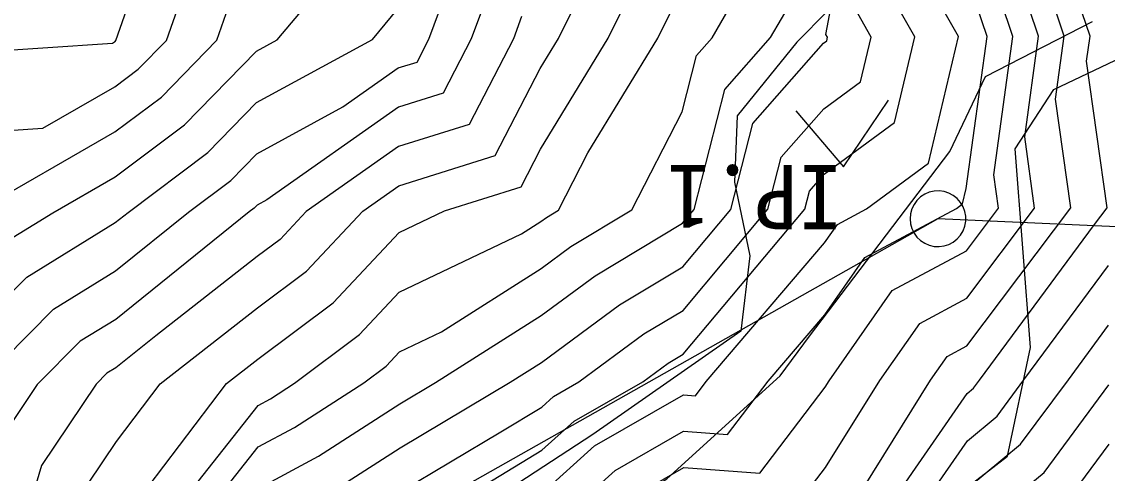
# Model space of a CAD drawing. Extents: x 42655 to 43811, y -141820 to -141156.
# Drawn here: x 43241.93 to 43280.88, y -141342.18 to -141325.97 of the extents above; entities that cross this region are included whole.
import ezdxf

# ---------------------------------------------------------------- set-up
doc = ezdxf.new("R2010")
doc.units = 0
for name, color, linetype in [('D-BMK-HTXT_1', 7, 'Continuous'), ('ZE_HICN', 7, 'Continuous'), ('ZE_LWCN', 7, 'Continuous'), ('地形', 7, 'Continuous')]:
    doc.layers.add(name, color=color, linetype=linetype)

msp = doc.modelspace()

# ---------------------------------------------------------------- linework, layer by layer
at = {"layer": 'D-BMK-HTXT_1'}
for p, q in [((43274.802, -141333.044), (43130.975, -141414.265)), ((43439.808, -141340.537), (43274.802, -141333.044))]:
    msp.add_line(p, q, dxfattribs=at)
msp.add_lwpolyline([(43273.802, -141333.044), (43273.818, -141333.222), (43273.866, -141333.395), (43273.944, -141333.557), (43274.049, -141333.702), (43274.179, -141333.826), (43274.328, -141333.924), (43274.493, -141333.995), (43274.668, -141334.035), (43274.847, -141334.043), (43275.025, -141334.019), (43275.195, -141333.963), (43275.353, -141333.878), (43275.493, -141333.766), (43275.611, -141333.631), (43275.703, -141333.478), (43275.766, -141333.31), (43275.798, -141333.133), (43275.798, -141332.954), (43275.766, -141332.778), (43275.703, -141332.61), (43275.611, -141332.456), (43275.493, -141332.321), (43275.353, -141332.209), (43275.195, -141332.124), (43275.025, -141332.069), (43274.847, -141332.045), (43274.668, -141332.053), (43274.493, -141332.093), (43274.328, -141332.163), (43274.179, -141332.262), (43274.049, -141332.386), (43273.944, -141332.531), (43273.866, -141332.692), (43273.818, -141332.865), (43273.802, -141333.044)], dxfattribs=at)
at = {"layer": 'ZE_HICN'}
for points in [[(43241.9, -141357.482), (43242.545, -141354.033), (43242.859, -141351.315), (43244.774, -141345.842), (43244.841, -141345.143), (43244.975, -141344.693), (43245.343, -141344.144), (43249.284, -141338.959), (43250.403, -141338.087), (43253.103, -141336.06), (43255.47, -141333.538), (43257.102, -141332.76), (43259.846, -141331.894), (43260.544, -141330.544), (43262.971, -141326.569), (43265.588, -141321.254)], [(43249.689, -141374.859), (43250.57, -141373.588), (43252.624, -141369.757), (43253.076, -141366.667), (43253.74, -141363.589), (43254.854, -141358.308), (43255.054, -141357.42), (43255.176, -141356.93), (43255.574, -141355.76), (43257.228, -141351.247), (43258.712, -141348.917), (43260.625, -141347.681), (43263.355, -141345.055), (43264.697, -141343.841), (43265.692, -141343.273), (43269.564, -141343.552), (43270.774, -141341.968), (43272.722, -141338.849), (43274.151, -141336.8), (43275.833, -141335.898), (43278.271, -141332.66), (43277.915, -141330.107), (43278.412, -141326.496), (43276.737, -141321.518)], [(43240.222, -141337.046), (43242.119, -141335.138), (43245.292, -141333.18), (43245.747, -141332.813), (43248.609, -141330.669), (43250.36, -141328.873), (43254.515, -141326.609), (43255.432, -141325.517)], [(43255.514, -141342.839), (43259.123, -141340.691), (43260.587, -141339.802), (43261.011, -141339.419), (43261.919, -141338.9), (43264.25, -141337.177), (43265.659, -141336.332), (43268.703, -141332.705), (43269.18, -141330.836), (43270.713, -141329.097), (43272.029, -141328.126), (43272.408, -141326.525), (43271.711, -141325.298)], [(43255.992, -141375.904), (43258.278, -141372.907), (43260.154, -141369.721), (43260.702, -141364.205), (43260.778, -141363.65), (43260.782, -141363.556), (43260.851, -141363.37), (43263.775, -141357.379), (43264.16, -141355.452), (43265.75, -141355.603), (43268.727, -141354.803), (43269.864, -141351.187), (43270.813, -141350.209), (43274.319, -141349.256), (43275.461, -141344.998), (43275.874, -141344.402), (43278.608, -141342.146), (43280.936, -141339.002)]]:
    msp.add_lwpolyline(points, dxfattribs=at)
at = {"layer": 'ZE_LWCN'}
for points in [[(43240.175, -141327.08), (43245.186, -141326.744), (43245.261, -141326.701), (43245.286, -141326.683), (43245.315, -141326.652), (43246.81, -141322.384), (43248.943, -141320.473), (43247.199, -141318.085), (43247.631, -141314.316), (43246.886, -141312.269), (43245.187, -141310.867), (43243.771, -141308.172), (43243.443, -141304.083), (43240.962, -141302.022)], [(43253.438, -141342.59), (43255.506, -141341.262), (43259.458, -141338.911), (43260.58, -141338.199), (43263.379, -141336.132), (43265.652, -141334.768), (43267.378, -141332.711), (43268.167, -141329.62), (43270.702, -141326.745), (43270.811, -141326.664), (43270.842, -141326.532), (43270.785, -141326.431), (43271.933, -141320.364)], [(43263.96, -141342.957), (43265.686, -141341.97), (43268.409, -141342.166), (43270.76, -141339.088), (43270.905, -141338.857), (43273.165, -141335.617), (43275.825, -141334.191), (43276.973, -141332.666), (43276.806, -141331.464), (43277.488, -141326.501), (43275.765, -141321.378)], [(43241.16, -141333.989), (43243.045, -141332.826), (43245.284, -141331.541), (43247.778, -141329.672), (43250.351, -141327.033), (43251.1, -141326.625), (43255.413, -141321.489)], [(43240.379, -141339.001), (43243.077, -141336.288), (43245.3, -141334.916), (43247.921, -141332.803), (43249.439, -141331.665), (43250.368, -141330.713), (43253.452, -141329.033), (43255.442, -141327.634), (43256.118, -141327.421), (43256.543, -141326.6), (43257.773, -141323.279)], [(43260.602, -141342.891), (43262.486, -141341.188), (43265.673, -141339.364), (43266.099, -141339.395), (43266.493, -141338.878), (43270.736, -141333.907), (43271.194, -141333.251), (43272.244, -141332.688), (43274.466, -141331.049), (43275.539, -141326.51), (43273.564, -141323.032)], [(43240.363, -141367.073), (43242.073, -141365.722), (43242.784, -141363.64), (43243.351, -141359.979), (43244.112, -141357.471), (43244.35, -141356.199), (43244.915, -141351.305), (43245.371, -141350.001), (43247.014, -141347.139), (43247.341, -141345.131), (43250.418, -141341.231), (43251.721, -141340.53), (43254.205, -141338.936), (43255.002, -141338.338), (43255.49, -141337.817), (43256.99, -141337.102), (43260.564, -141334.831), (43261.635, -141334.04), (43263.823, -141332.728), (43265.626, -141329.205), (43266.14, -141327.189), (43266.702, -141326.552), (43268.346, -141323.708)], [(43250.656, -141375.837), (43253.918, -141369.751), (43254.177, -141367.987), (43255.126, -141363.582), (43255.601, -141361.333), (43256.265, -141358.237), (43256.781, -141357.412), (43257.326, -141355.285), (43258.808, -141351.24), (43259.605, -141349.988), (43260.632, -141349.325), (43265.079, -141345.047), (43265.435, -141344.726), (43265.698, -141344.575), (43270.719, -141344.937), (43270.787, -141344.848), (43274.539, -141338.84), (43275.137, -141337.982), (43275.841, -141337.605), (43279.569, -141332.654), (43279.024, -141328.751), (43279.335, -141326.492), (43278.288, -141323.378)], [(43240.189, -141329.959), (43242.694, -141329.792), (43245.269, -141328.314), (43246.117, -141327.679), (43247.126, -141326.644), (43248.083, -141323.911)], [(43256.606, -141343.769), (43260.595, -141341.346), (43261.748, -141340.303), (43264.221, -141338.889), (43265.122, -141338.223), (43265.667, -141337.896), (43270.028, -141332.699), (43270.193, -141332.051), (43270.724, -141331.449), (43273.248, -141329.587), (43273.973, -141326.517), (43272.638, -141324.165)], [(43260.609, -141344.435), (43263.223, -141342.072), (43265.68, -141340.667), (43267.254, -141340.78), (43268.715, -141338.868), (43270.748, -141336.486), (43272.18, -141334.434), (43275.464, -141332.673), (43275.684, -141332.511), (43275.815, -141331.958), (43276.565, -141326.505), (43275.778, -141324.167)], [(43258.819, -141324.535), (43258.057, -141326.592), (43257.05, -141328.539), (43255.449, -141329.044), (43250.732, -141332.359), (43250.377, -141332.552), (43250.27, -141332.662), (43250.095, -141332.793), (43245.308, -141336.652), (43244.035, -141337.437), (43242.49, -141338.991), (43241.478, -141340.498)], [(43241.594, -141362.127), (43243.006, -141357.477), (43243.448, -141355.116), (43243.887, -141351.31), (43245.357, -141347.108), (43246.022, -141345.949), (43246.155, -141345.136), (43250.411, -141339.743), (43250.862, -141339.5), (43251.723, -141338.948), (43254.052, -141337.199), (43255.48, -141335.677), (43259.864, -141333.587), (43260.556, -141333.147), (43260.763, -141332.994), (43261.187, -141332.74), (43262.241, -141330.681), (43264.756, -141326.561), (43265.605, -141324.837)], [(43241.831, -141351.32), (43242.98, -141348.036), (43243.256, -141345.15), (43243.81, -141343.294), (43245.329, -141341.032), (43246.896, -141338.97), (43250.394, -141336.242), (43252.153, -141334.921), (43254.169, -141332.773), (43255.462, -141331.865), (43258.914, -141330.775), (43260.53, -141327.651), (43261.186, -141326.578), (43262.182, -141324.555)], [(43240.373, -141369.074), (43243.082, -141366.933), (43244.209, -141363.634), (43245.108, -141357.831), (43245.218, -141357.466), (43245.253, -141357.281), (43245.399, -141356.01), (43246.301, -141351.298), (43248.006, -141348.329), (43248.527, -141345.125), (43250.425, -141342.72), (43252.579, -141341.56), (43255.499, -141339.686), (43256.781, -141338.924), (43260.572, -141336.515), (43262.507, -141335.086), (43265.644, -141333.204), (43266.053, -141332.717), (43267.153, -141328.404), (43268.796, -141326.542), (43269.579, -141325.187)], [(43271.903, -141345.015), (43275.85, -141339.309), (43276.083, -141339.117), (43276.294, -141338.832), (43280.417, -141333.246), (43280.867, -141332.648), (43280.134, -141327.394), (43280.259, -141326.488), (43279.838, -141325.239)], [(43240.202, -141332.839), (43245.277, -141329.927), (43246.947, -141328.676), (43248.937, -141326.635), (43249.356, -141325.438)], [(43259.866, -141325.79), (43259.571, -141326.585), (43257.982, -141329.657), (43255.455, -141330.455), (43252.142, -141332.783), (43251.204, -141333.782), (43250.386, -141334.396), (43246.741, -141337.239), (43245.316, -141338.388), (43244.993, -141338.587), (43244.601, -141338.981), (43242.644, -141341.896), (43241.671, -141345.158)], [(43253.251, -141375.916), (43255.648, -141371.394), (43256.302, -141370.537), (43256.773, -141369.737), (43256.929, -141368.166), (43257.937, -141363.569), (43258.505, -141360.923), (43260.671, -141357.456), (43260.701, -141357.393), (43261.682, -141352.479), (43265.737, -141352.864), (43266.859, -141352.562), (43267.288, -141351.2), (43270.8, -141347.575), (43272.527, -141347.106), (43273.089, -141345.01), (43275.858, -141341.007), (43276.925, -141340.126), (43277.889, -141338.824), (43280.916, -141334.723)], [(43254.572, -141375.91), (43255.66, -141373.859), (43257.29, -141371.722), (43258.463, -141369.729), (43258.853, -141365.814), (43259.346, -141363.562), (43259.624, -141362.267), (43260.685, -141360.568), (43262.238, -141357.386), (43262.921, -141353.966), (43265.744, -141354.233), (43267.793, -141353.683), (43268.576, -141351.194), (43270.807, -141348.892), (43273.423, -141348.181), (43274.275, -141345.004), (43275.866, -141342.705), (43277.766, -141341.136), (43279.484, -141338.817), (43280.926, -141336.863)], [(43257.891, -141375.895), (43259.266, -141374.092), (43260.737, -141371.593), (43262.241, -141369.711), (43262.746, -141366.011), (43262.85, -141363.546), (43264.655, -141358.718), (43265.313, -141357.372), (43265.399, -141356.938), (43265.756, -141356.972), (43269.66, -141355.923), (43270.822, -141352.23), (43272.102, -141351.177), (43275.215, -141350.331), (43275.89, -141347.817), (43277.226, -141344.99), (43279.449, -141343.155), (43280.946, -141341.134)]]:
    msp.add_lwpolyline(points, dxfattribs=at)
at = {"layer": '地形'}
for points in [[(43273.079, -141323.322), (43269.743, -141326.702), (43267.594, -141329.35), (43267.503, -141331.725), (43268.052, -141334.374), (43267.728, -141337.079), (43262.426, -141340.779), (43256.21, -141344.843), (43254.244, -141347.766), (43251.365, -141351.191), (43254.566, -141352.527)], [(43259.49, -141353.323), (43254.566, -141352.527), (43255.16, -141350.289), (43257.446, -141347.275), (43265.079, -141342.38), (43269.147, -141338.68), (43270.2, -141337.253), (43275.228, -141330.629), (43276.508, -141327.935), (43280.347, -141325.971)], [(43294.351, -141331.831), (43287.212, -141332.387), (43284.616, -141334.517), (43283.225, -141336.926), (43283.04, -141340.261), (43281.649, -141344.615), (43277.477, -141350.173), (43268.484, -141357.862), (43265.795, -141360.456), (43262.364, -141362.216), (43259.675, -141361.29), (43259.954, -141358.047), (43259.49, -141353.323), (43267.278, -141348.135), (43273.583, -141344.43), (43277.292, -141341.558), (43278.126, -141337.667), (43277.57, -141330.534), (43278.96, -141328.403), (43282.854, -141326.551), (43290.086, -141326.643), (43295.186, -141327.014), (43294.351, -141331.831)], [(43269.704, -141329.176), (43271.412, -141331.179), (43273.032, -141328.79)]]:
    msp.add_lwpolyline(points, dxfattribs=at)

# ---------------------------------------------------------------- texts
at = {"layer": 'D-BMK-HTXT_1'}
msp.add_text('IP.1', height=2.3065, rotation=179.9992, dxfattribs=at).set_placement((43271.355, -141331.119))

doc.saveas('drawing.dxf')
